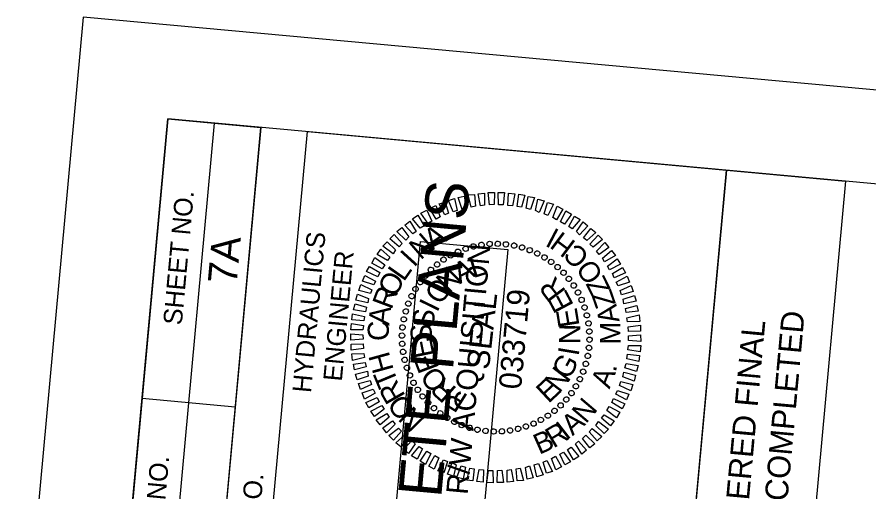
# Model space of a CAD drawing. Extents: x 2011671 to 2012922, y 444832 to 446720.
# Drawn here: x 2011808.5 to 2012036.3, y 446593.3 to 446720.2 of the extents above; entities that cross this region are included whole.
import ezdxf

# ---------------------------------------------------------------- set-up
doc = ezdxf.new("R2010")
doc.units = 0
for name, color, linetype in [('Sheet Data Field CELL', 7, 'Continuous'), ('Sheet Plan And Profile CELL', 7, 'Continuous'), ('Sheet Plot Border Outside CELL', 7, 'Continuous'), ('Sheet Professional Seal CELL', 7, 'Continuous'), ('Sheet Profile Grid Minor CELL', 7, 'Continuous'), ('Sheet Sticker Exception Certification CELL', 7, 'Continuous'), ('Sheet Sticker Incomplete CELL', 7, 'Continuous')]:
    doc.layers.add(name, color=color, linetype=linetype)

msp = doc.modelspace()

# ---------------------------------------------------------------- linework, layer by layer
at = {"layer": 'Sheet Plan And Profile CELL'}
for p, q in [((2011842.98, 446492.7), (2011861.29, 446691.91)), ((2011855.42, 446491.55), (2011873.74, 446690.76)), ((2011841.98, 446618.37), (2011866.87, 446616.08))]:
    msp.add_line(p, q, dxfattribs=at)
for points in [[(2011848.79, 446693.05), (2011711.46, 445199.36), (2012757.04, 445103.22), (2012894.38, 446596.92)], [(2011830.48, 446493.85), (2011848.79, 446693.05), (2011873.74, 446690.76), (2011855.42, 446491.55)], [(2011877.03, 446590.04), (2011886.19, 446689.62), (2011998.21, 446679.32), (2011989.06, 446579.74)]]:
    msp.add_lwpolyline(points, close=True, dxfattribs=at)
at = {"layer": 'Sheet Plot Border Outside CELL'}
msp.add_lwpolyline([(2012765.92, 444926.66), (2012921.57, 446619.52), (2011826.19, 446720.24), (2011670.54, 445027.38)], close=True, dxfattribs=at)
at = {"layer": 'Sheet Professional Seal CELL'}
for p, q in [((2011928.46, 446658.36), (2011928.46, 446658.36)), ((2011930.53, 446658.97), (2011930.53, 446658.97)), ((2011932.67, 446659.38), (2011932.67, 446659.38)), ((2011934.9, 446659.57), (2011934.9, 446659.57)), ((2011937.07, 446659.68), (2011937.07, 446659.68)), ((2011939.26, 446659.52), (2011939.26, 446659.52)), ((2011941.44, 446659.17), (2011941.44, 446659.17)), ((2011943.55, 446658.63), (2011943.55, 446658.63)), ((2011945.6, 446657.99), (2011945.6, 446657.99)), ((2011922.57, 446655.48), (2011922.57, 446655.48)), ((2011924.43, 446656.57), (2011924.43, 446656.57)), ((2011926.43, 446657.54), (2011926.43, 446657.54)), ((2011947.63, 446657.1), (2011947.63, 446657.1)), ((2011949.54, 446656.02), (2011949.54, 446656.02)), ((2011920.79, 446654.14), (2011920.79, 446654.14)), ((2011951.39, 446654.84), (2011951.39, 446654.84)), ((2011953.06, 446653.43), (2011953.06, 446653.43)), ((2011917.65, 446651.12), (2011917.65, 446651.12)), ((2011919.16, 446652.74), (2011919.16, 446652.74)), ((2011954.68, 446651.93), (2011954.68, 446651.93)), ((2011916.24, 446649.44), (2011916.24, 446649.44)), ((2011956.09, 446650.29), (2011956.09, 446650.29)), ((2011915.07, 446647.59), (2011915.07, 446647.59)), ((2011957.43, 446648.51), (2011957.43, 446648.51)), ((2011958.52, 446646.66), (2011958.52, 446646.66)), ((2011913.99, 446645.68), (2011913.99, 446645.68)), ((2011959.49, 446644.66), (2011959.49, 446644.66)), ((2011913.1, 446643.65), (2011913.1, 446643.65)), ((2011960.3, 446642.63), (2011960.3, 446642.63)), ((2011911.91, 446639.49), (2011911.91, 446639.49)), ((2011912.46, 446641.6), (2011912.46, 446641.6)), ((2011960.92, 446640.56), (2011960.92, 446640.56)), ((2011911.56, 446637.32), (2011911.56, 446637.32)), ((2011961.32, 446638.42), (2011961.32, 446638.42)), ((2011911.41, 446635.12), (2011911.41, 446635.12)), ((2011961.52, 446636.19), (2011961.52, 446636.19)), ((2011911.51, 446632.95), (2011911.51, 446632.95)), ((2011936.52, 446634.57), (2011936.52, 446634.57)), ((2011961.62, 446634.02), (2011961.62, 446634.02)), ((2011911.71, 446630.73), (2011911.71, 446630.73)), ((2011961.47, 446631.82), (2011961.47, 446631.82)), ((2011912.12, 446628.58), (2011912.12, 446628.58)), ((2011961.12, 446629.65), (2011961.12, 446629.65)), ((2011912.73, 446626.51), (2011912.73, 446626.51)), ((2011960.57, 446627.54), (2011960.57, 446627.54)), ((2011913.55, 446624.48), (2011913.55, 446624.48)), ((2011959.93, 446625.49), (2011959.93, 446625.49)), ((2011914.52, 446622.48), (2011914.52, 446622.48)), ((2011957.96, 446621.55), (2011957.96, 446621.55)), ((2011959.04, 446623.46), (2011959.04, 446623.46)), ((2011915.6, 446620.63), (2011915.6, 446620.63)), ((2011956.79, 446619.7), (2011956.79, 446619.7)), ((2011916.94, 446618.85), (2011916.94, 446618.85)), ((2011918.35, 446617.21), (2011918.35, 446617.21)), ((2011955.38, 446618.02), (2011955.38, 446618.02)), ((2011919.97, 446615.71), (2011919.97, 446615.71)), ((2011952.24, 446615), (2011952.24, 446615)), ((2011953.88, 446616.4), (2011953.88, 446616.4)), ((2011921.65, 446614.3), (2011921.65, 446614.3)), ((2011923.5, 446613.12), (2011923.5, 446613.12)), ((2011948.6, 446612.57), (2011948.6, 446612.57)), ((2011950.46, 446613.66), (2011950.46, 446613.66)), ((2011925.41, 446612.04), (2011925.41, 446612.04)), ((2011927.43, 446611.15), (2011927.43, 446611.15)), ((2011929.48, 446610.51), (2011929.48, 446610.51)), ((2011931.59, 446609.97), (2011931.59, 446609.97)), ((2011942.51, 446610.17), (2011942.51, 446610.17)), ((2011944.57, 446610.78), (2011944.57, 446610.78)), ((2011946.61, 446611.6), (2011946.61, 446611.6)), ((2011933.77, 446609.62), (2011933.77, 446609.62)), ((2011935.97, 446609.47), (2011935.97, 446609.47)), ((2011938.13, 446609.57), (2011938.13, 446609.57)), ((2011940.36, 446609.76), (2011940.36, 446609.76))]:
    msp.add_line(p, q, dxfattribs=at)
for points in [[(2011925.09, 446668.16), (2011923.87, 446671.23), (2011925.52, 446671.73), (2011926.23, 446668.55)], [(2011927.52, 446668.84), (2011926.5, 446671.99), (2011928.09, 446672.4), (2011928.61, 446669.24)], [(2011929.98, 446669.42), (2011929.13, 446672.71), (2011930.8, 446672.85), (2011931.06, 446669.67)], [(2011932.42, 446669.79), (2011931.77, 446673.02), (2011933.49, 446673.16), (2011933.5, 446670)], [(2011934.86, 446670.02), (2011934.46, 446673.32), (2011936.16, 446673.32), (2011936.07, 446670.11)], [(2011937.27, 446670.1), (2011937.17, 446673.37), (2011938.87, 446673.32), (2011938.48, 446670.09)], [(2011939.77, 446669.92), (2011939.92, 446673.17), (2011941.61, 446673.02), (2011940.96, 446669.81)], [(2011942.25, 446669.64), (2011942.65, 446672.87), (2011944.28, 446672.62), (2011943.44, 446669.43)], [(2011944.62, 446669.17), (2011945.21, 446672.33), (2011946.89, 446671.98), (2011945.79, 446668.81)], [(2011947.12, 446668.54), (2011947.8, 446671.59), (2011949.46, 446671.09), (2011948.13, 446668.05)], [(2011920.55, 446666.27), (2011918.9, 446669.08), (2011920.48, 446669.89), (2011921.61, 446666.87)], [(2011922.86, 446667.36), (2011921.37, 446670.31), (2011922.98, 446670.81), (2011923.86, 446667.87)], [(2011949.45, 446667.67), (2011950.38, 446670.7), (2011951.99, 446670.2), (2011950.46, 446667.18)], [(2011951.77, 446666.71), (2011952.95, 446669.71), (2011954.44, 446668.92), (2011952.77, 446666.06)], [(2011916.31, 446663.84), (2011914.28, 446666.34), (2011915.72, 446667.26), (2011917.37, 446664.45)], [(2011918.39, 446665.16), (2011916.52, 446667.79), (2011918.06, 446668.6), (2011919.39, 446665.67)], [(2011953.87, 446665.51), (2011955.3, 446668.49), (2011956.78, 446667.6), (2011954.92, 446664.91)], [(2011956.07, 446664.3), (2011957.58, 446667.03), (2011959.05, 446666.14), (2011956.96, 446663.62)], [(2011914.36, 446662.27), (2011912.22, 446664.62), (2011913.52, 446665.71), (2011915.22, 446662.94)], [(2011958.1, 446662.91), (2011959.85, 446665.56), (2011961.15, 446664.44), (2011958.93, 446662.03)], [(2011912.45, 446660.63), (2011910.05, 446662.91), (2011911.36, 446664), (2011913.29, 446661.51)], [(2011959.96, 446661.24), (2011961.9, 446663.77), (2011963.25, 446662.69), (2011960.84, 446660.5)], [(2011909.05, 446656.98), (2011906.33, 446658.99), (2011907.49, 446660.19), (2011909.75, 446658.02)], [(2011910.73, 446658.88), (2011908.17, 446660.98), (2011909.38, 446662.17), (2011911.52, 446659.76)], [(2011961.71, 446659.57), (2011963.89, 446661.98), (2011965.08, 446660.76), (2011962.54, 446658.79)], [(2011963.44, 446657.65), (2011965.72, 446660), (2011966.75, 446658.65), (2011964.17, 446656.78)], [(2011907.53, 446655.16), (2011904.82, 446656.77), (2011905.8, 446658.18), (2011908.21, 446656.05)], [(2011965.03, 446655.85), (2011967.43, 446657.84), (2011968.51, 446656.53), (2011965.64, 446654.84)], [(2011906.17, 446652.98), (2011903.35, 446654.49), (2011904.19, 446655.97), (2011906.82, 446654.02)], [(2011966.39, 446653.71), (2011968.98, 446655.64), (2011969.9, 446654.2), (2011966.96, 446652.71)], [(2011905.02, 446650.82), (2011901.99, 446652.26), (2011902.72, 446653.59), (2011905.48, 446651.94)], [(2011967.71, 446651.69), (2011970.42, 446653.29), (2011971.25, 446651.91), (2011968.21, 446650.54)], [(2011903.92, 446648.66), (2011900.9, 446649.69), (2011901.54, 446651.19), (2011904.36, 446649.68)], [(2011968.76, 446649.38), (2011971.62, 446650.98), (2011972.27, 446649.36), (2011969.27, 446648.38)], [(2011903.05, 446646.33), (2011899.86, 446647.13), (2011900.42, 446648.79), (2011903.4, 446647.36)], [(2011969.76, 446647.13), (2011972.69, 446648.47), (2011973.25, 446646.86), (2011970.1, 446645.99)], [(2011902.27, 446643.84), (2011899.13, 446644.59), (2011899.53, 446646.21), (2011902.53, 446645.03)], [(2011970.6, 446644.84), (2011973.61, 446645.87), (2011974.07, 446644.32), (2011970.78, 446643.57)], [(2011901.65, 446641.49), (2011898.44, 446641.99), (2011898.89, 446643.6), (2011901.96, 446642.67)], [(2011971.17, 446642.33), (2011974.27, 446643.2), (2011974.57, 446641.62), (2011971.42, 446641.25)], [(2011901.28, 446639.02), (2011898.04, 446639.31), (2011898.24, 446640.95), (2011901.44, 446640.21)], [(2011971.6, 446639.88), (2011974.83, 446640.64), (2011975.03, 446638.91), (2011971.75, 446638.81)], [(2011901.01, 446636.63), (2011897.75, 446636.68), (2011897.95, 446638.32), (2011901.17, 446637.82)], [(2011971.93, 446637.44), (2011975.19, 446637.94), (2011975.19, 446636.29), (2011971.97, 446636.23)], [(2011901.03, 446634.12), (2011897.79, 446633.86), (2011897.75, 446635.57), (2011900.99, 446635.33)], [(2011972.01, 446635.02), (2011975.24, 446635.28), (2011975.29, 446633.57), (2011972.05, 446633.81)], [(2011901.11, 446631.7), (2011897.85, 446631.2), (2011897.85, 446632.85), (2011901.07, 446632.91)], [(2011901.43, 446629.26), (2011898.2, 446628.5), (2011898.01, 446630.23), (2011901.28, 446630.33)], [(2011972.03, 446632.51), (2011975.29, 446632.46), (2011975.09, 446630.82), (2011971.87, 446631.32)], [(2011971.76, 446630.12), (2011974.99, 446629.83), (2011974.79, 446628.19), (2011971.6, 446628.93)], [(2011901.86, 446626.81), (2011898.77, 446625.94), (2011898.46, 446627.52), (2011901.61, 446627.89)], [(2011971.38, 446627.65), (2011974.6, 446627.15), (2011974.15, 446625.54), (2011971.07, 446626.47)], [(2011902.43, 446624.3), (2011899.43, 446623.27), (2011898.97, 446624.82), (2011902.25, 446625.57)], [(2011970.76, 446625.3), (2011973.91, 446624.55), (2011973.51, 446622.93), (2011970.5, 446624.11)], [(2011903.28, 446622.01), (2011900.34, 446620.67), (2011899.79, 446622.28), (2011902.93, 446623.15)], [(2011969.98, 446622.81), (2011973.17, 446622.01), (2011972.62, 446620.36), (2011969.63, 446621.78)], [(2011904.28, 446619.76), (2011901.42, 446618.17), (2011900.76, 446619.78), (2011903.76, 446620.76)], [(2011969.11, 446620.48), (2011972.13, 446619.45), (2011971.49, 446617.95), (2011968.67, 446619.46)], [(2011905.32, 446617.45), (2011902.61, 446615.85), (2011901.78, 446617.23), (2011904.82, 446618.61)], [(2011968.01, 446618.32), (2011971.04, 446616.88), (2011970.32, 446615.55), (2011967.56, 446617.21)], [(2011906.64, 446615.43), (2011904.05, 446613.5), (2011903.13, 446614.94), (2011906.08, 446616.43)], [(2011966.86, 446616.16), (2011969.68, 446614.65), (2011968.84, 446613.17), (2011966.21, 446615.12)], [(2011908, 446613.29), (2011905.61, 446611.3), (2011904.52, 446612.61), (2011907.39, 446614.3)], [(2011909.59, 446611.49), (2011907.32, 446609.14), (2011906.28, 446610.49), (2011908.87, 446612.36)], [(2011963.98, 446612.16), (2011966.71, 446610.15), (2011965.54, 446608.95), (2011963.28, 446611.12)], [(2011965.5, 446613.98), (2011968.22, 446612.37), (2011967.23, 446610.96), (2011964.82, 446613.09)], [(2011911.32, 446609.57), (2011909.14, 446607.16), (2011907.95, 446608.38), (2011910.49, 446610.35)], [(2011962.3, 446610.26), (2011964.87, 446608.16), (2011963.65, 446606.97), (2011961.51, 446609.38)], [(2011913.08, 446607.9), (2011911.14, 446605.37), (2011909.78, 446606.45), (2011912.19, 446608.64)], [(2011960.58, 446608.51), (2011962.98, 446606.23), (2011961.68, 446605.14), (2011959.75, 446607.63)], [(2011914.93, 446606.23), (2011913.18, 446603.58), (2011911.88, 446604.7), (2011914.11, 446607.11)], [(2011916.96, 446604.84), (2011915.46, 446602.11), (2011913.98, 446603), (2011916.07, 446605.52)], [(2011956.72, 446605.3), (2011958.75, 446602.8), (2011957.31, 446601.88), (2011955.66, 446604.69)], [(2011958.67, 446606.88), (2011960.82, 446604.52), (2011959.51, 446603.43), (2011957.81, 446606.2)], [(2011919.16, 446603.63), (2011917.73, 446600.65), (2011916.26, 446601.54), (2011918.11, 446604.23)], [(2011921.26, 446602.43), (2011920.08, 446599.43), (2011918.6, 446600.22), (2011920.26, 446603.08)], [(2011954.64, 446603.98), (2011956.51, 446601.35), (2011954.98, 446600.54), (2011953.64, 446603.47)], [(2011923.58, 446601.47), (2011922.65, 446598.44), (2011921.04, 446598.94), (2011922.57, 446601.96)], [(2011925.91, 446600.6), (2011925.23, 446597.55), (2011923.57, 446598.05), (2011924.9, 446601.09)], [(2011947.94, 446600.98), (2011949.16, 446597.91), (2011947.51, 446597.41), (2011946.8, 446600.59)], [(2011950.17, 446601.78), (2011951.66, 446598.83), (2011950.06, 446598.33), (2011949.17, 446601.27)], [(2011952.48, 446602.88), (2011954.13, 446600.06), (2011952.55, 446599.25), (2011951.42, 446602.27)], [(2011928.41, 446599.97), (2011927.82, 446596.81), (2011926.15, 446597.16), (2011927.24, 446600.33)], [(2011930.78, 446599.5), (2011930.38, 446596.27), (2011928.75, 446596.52), (2011929.6, 446599.71)], [(2011933.27, 446599.22), (2011933.12, 446595.97), (2011931.43, 446596.12), (2011932.07, 446599.33)], [(2011935.76, 446599.04), (2011935.86, 446595.77), (2011934.16, 446595.82), (2011934.56, 446599.05)], [(2011938.18, 446599.12), (2011938.58, 446595.82), (2011936.87, 446595.83), (2011936.96, 446599.03)], [(2011940.61, 446599.35), (2011941.27, 446596.12), (2011939.55, 446595.98), (2011939.54, 446599.14)], [(2011943.05, 446599.73), (2011943.91, 446596.43), (2011942.24, 446596.29), (2011941.98, 446599.47)], [(2011945.52, 446600.3), (2011946.53, 446597.15), (2011944.94, 446596.74), (2011944.43, 446599.9)]]:
    msp.add_lwpolyline(points, close=True, dxfattribs=at)
for centre, major_axis in [((2011932.7, 446659.36), (-0.109, 0.712)), ((2011934.88, 446659.6), (-0.047, 0.718)), ((2011937.07, 446659.64), (0.016, 0.72)), ((2011939.25, 446659.5), (0.078, 0.716)), ((2011941.41, 446659.17), (0.141, 0.706)), ((2011926.42, 446657.53), (-0.29, 0.659)), ((2011928.46, 446658.32), (-0.231, 0.682)), ((2011930.56, 446658.93), (-0.171, 0.699)), ((2011943.54, 446658.65), (0.202, 0.691)), ((2011945.61, 446657.94), (0.261, 0.671)), ((2011947.61, 446657.06), (0.318, 0.646)), ((2011922.58, 446655.42), (-0.4, 0.599)), ((2011924.45, 446656.56), (-0.346, 0.631)), ((2011949.53, 446656.01), (0.374, 0.616)), ((2011951.35, 446654.79), (0.426, 0.581)), ((2011919.17, 446652.69), (-0.498, 0.52)), ((2011920.82, 446654.13), (-0.451, 0.562)), ((2011953.05, 446653.43), (0.475, 0.541)), ((2011917.66, 446651.11), (-0.541, 0.475)), ((2011954.63, 446651.91), (0.52, 0.498)), ((2011956.08, 446650.27), (0.562, 0.451)), ((2011916.29, 446649.4), (-0.581, 0.426)), ((2011957.37, 446648.5), (0.599, 0.4)), ((2011914.02, 446645.66), (-0.646, 0.318)), ((2011915.08, 446647.58), (-0.616, 0.374)), ((2011958.51, 446646.63), (0.631, 0.346)), ((2011913.14, 446643.66), (-0.671, 0.261)), ((2011959.47, 446644.67), (0.659, 0.29)), ((2011912.44, 446641.59), (-0.691, 0.202)), ((2011960.27, 446642.63), (0.682, 0.231)), ((2011911.92, 446639.46), (-0.706, 0.141)), ((2011960.88, 446640.53), (0.699, 0.171)), ((2011911.59, 446637.3), (-0.716, 0.078)), ((2011961.3, 446638.38), (0.712, 0.109)), ((2011911.44, 446635.12), (-0.72, 0.016)), ((2011961.54, 446636.21), (0.718, 0.047)), ((2011911.49, 446632.93), (-0.718, -0.047)), ((2011961.59, 446634.02), (0.72, -0.016)), ((2011911.73, 446630.76), (-0.712, -0.109)), ((2011961.11, 446629.68), (0.706, -0.141)), ((2011961.45, 446631.84), (0.716, -0.078)), ((2011912.15, 446628.61), (-0.699, -0.171)), ((2011960.59, 446627.55), (0.691, -0.202)), ((2011912.77, 446626.51), (-0.682, -0.231)), ((2011959.89, 446625.48), (0.671, -0.261)), ((2011913.56, 446624.47), (-0.659, -0.29)), ((2011959.01, 446623.48), (0.646, -0.318)), ((2011914.53, 446622.51), (-0.631, -0.346)), ((2011915.66, 446620.64), (-0.599, -0.4)), ((2011957.96, 446621.56), (0.616, -0.374)), ((2011916.96, 446618.87), (-0.562, -0.451)), ((2011956.74, 446619.74), (0.581, -0.426)), ((2011918.4, 446617.23), (-0.52, -0.498)), ((2011953.86, 446616.45), (0.498, -0.52)), ((2011955.37, 446618.03), (0.541, -0.475)), ((2011919.98, 446615.72), (-0.475, -0.541)), ((2011921.69, 446614.35), (-0.426, -0.581)), ((2011950.45, 446613.72), (0.4, -0.599)), ((2011952.21, 446615.01), (0.451, -0.562)), ((2011923.5, 446613.13), (-0.374, -0.616)), ((2011925.42, 446612.08), (-0.318, -0.646)), ((2011946.62, 446611.61), (0.29, -0.659)), ((2011948.58, 446612.58), (0.346, -0.631)), ((2011927.43, 446611.2), (-0.261, -0.671)), ((2011929.5, 446610.49), (-0.202, -0.691)), ((2011931.62, 446609.97), (-0.141, -0.706)), ((2011933.78, 446609.64), (-0.078, -0.716)), ((2011935.97, 446609.5), (-0.016, -0.72)), ((2011938.16, 446609.54), (0.047, -0.718)), ((2011940.33, 446609.78), (0.109, -0.712)), ((2011942.48, 446610.21), (0.171, -0.699)), ((2011944.58, 446610.82), (0.231, -0.682))]:
    msp.add_ellipse(centre, major_axis=major_axis, ratio=0.999708, dxfattribs=at)
at = {"layer": 'Sheet Sticker Exception Certification CELL'}
for p, q in [((2011979.88, 446480.11), (2011998.2, 446679.32)), ((2011998.21, 446679.32), (2012030.06, 446676.39)), ((2012030.04, 446676.39), (2012011.73, 446477.18))]:
    msp.add_line(p, q, dxfattribs=at)
at = {"layer": 'Sheet Sticker Incomplete CELL'}
msp.add_lwpolyline([(2011926.32, 446511.7), (2011902.91, 446513.85), (2011916.37, 446660.23), (2011939.77, 446658.08)], close=True, dxfattribs=at)

# ---------------------------------------------------------------- texts
at = {"layer": 'Sheet Data Field CELL'}
msp.add_text('7A', height=7.75, rotation=84.7467, dxfattribs=at).set_placement((2011867.21, 446648.68))
at = {"layer": 'Sheet Plan And Profile CELL'}
for s, height, p in [('SHEET NO.', 5, (2011852.55, 446637.78)), ('HYDRAULICS', 5, (2011887.09, 446619.69)), ('ENGINEER', 5, (2011895.35, 446622.75)), ('PROJECT REFERENCE NO.', 5.0001, (2011841.17, 446515.16)), ('R/W SHEET NO.', 5.0001, (2011869.8, 446547.47))]:
    msp.add_text(s, height=height, rotation=84.7467, dxfattribs=at).set_placement(p)
at = {"layer": 'Sheet Professional Seal CELL'}
for s, height, rotation, p in [('N', 5.64, 40.5656, (2011916.42, 446655.15)), ('A', 5.64, 33.3638, (2011919.62, 446657.81)), ('I', 5.64, 47.7668, (2011914.68, 446653.15)), ('L', 5.64, 17.1475, (2011930.49, 446650.44)), ('L', 5.64, 54.9675, (2011911.92, 446649.33)), ('N', 5.64, 45.2233, (2011924.03, 446646.21)), ('A', 5.64, 26.5069, (2011926.88, 446648.81)), ('O', 5.64, 62.1678, (2011909.67, 446645.12)), ('R', 5.64, 127.2281, (2011955.48, 446646.99)), ('O', 5.64, 54.5801, (2011921.73, 446643.06)), ('R', 5.64, 69.3678, (2011908.62, 446641.86)), ('E', 5.64, 117.8707, (2011957.5, 446643.24)), ('I', 5.64, 63.9363, (2011920.85, 446641.13)), ('SEAL', 5.998, 83.7467, (2011934.71, 446625.85)), ('A', 5.64, 83.767, (2011908.03, 446637.69)), ('S', 5.64, 82.6471, (2011919.76, 446636.91)), ('E', 5.64, 99.1584, (2011958.95, 446637.78)), ('C', 5.64, 90.9665, (2011907.97, 446633.73)), ('S', 5.64, 92.0023, (2011919.48, 446633.32)), ('N', 5.64, 89.803, (2011959.1, 446632.8)), ('E', 5.64, 101.3577, (2011920.21, 446629.79)), ('H', 5.64, 105.3661, (2011909.27, 446625.98)), ('I', 5.64, 80.4479, (2011958.64, 446629.47)), ('F', 5.64, 110.7137, (2011921.41, 446626.47)), ('G', 5.64, 61.7369, (2011956.15, 446623.12)), ('O', 5.64, 129.4279, (2011924.05, 446622.91)), ('N', 5.64, 52.3806, (2011953.56, 446619.55)), ('T', 5.64, 112.5664, (2011910.61, 446622.59)), ('R', 5.64, 138.7863, (2011926.33, 446620.95)), ('E', 5.64, 43.0235, (2011950.6, 446616.81)), ('R', 5.64, 119.7672, (2011912.49, 446619)), ('P', 5.64, 148.1455, (2011929.37, 446619.06)), ('O', 5.64, 126.9684, (2011915.26, 446615.29)), ('N', 5.64, 134.1702, (2011917.94, 446612.73))]:
    msp.add_text(s, height=height, rotation=rotation, dxfattribs=at).set_placement(p)
at = {"layer": 'Sheet Profile Grid Minor CELL'}
for s, height, rotation, p in [('I', 5.5, 152.3393, (2011953.84, 446663.16)), ('H', 5.5, 143.0945, (2011958.21, 446660)), ('C', 5.5, 134.2218, (2011961.87, 446656.35)), ('O', 5.5, 123.5173, (2011965.48, 446651.26)), ('Z', 5.5, 116.3905, (2011967.33, 446647.54)), ('033719', 5.998, 84.7467, (2011943.27, 446620.58)), ('Z', 5.5, 109.2637, (2011968.7, 446643.62)), ('A', 5.5, 101.0779, (2011969.66, 446638.94)), ('M', 5.5, 90.402, (2011969.89, 446632.73)), ('.', 5.5, 77.2217, (2011968.6, 446625.17)), ('A', 5.5, 69.0359, (2011966.93, 446620.7)), ('N', 5.5, 49.6591, (2011960.6, 446611.39)), ('I', 5.5, 37.9528, (2011955.4, 446606.99)), ('A', 5.5, 41.4733, (2011957.06, 446608.2)), ('B', 5.5, 23.8996, (2011948.14, 446603.23)), ('R', 5.5, 31.0264, (2011951.94, 446604.91))]:
    msp.add_text(s, height=height, rotation=rotation, dxfattribs=at).set_placement(p)
at = {"layer": 'Sheet Sticker Exception Certification CELL'}
for s, p in [('UNLESS ALL SIGNATURES COMPLETED', (2012004.66, 446483.75)), ('DOCUMENT NOT CONSIDERED FINAL', (2011994.97, 446490.4))]:
    msp.add_text(s, height=6.124, rotation=84.7467, dxfattribs=at).set_placement(p)
at = {"layer": 'Sheet Sticker Incomplete CELL'}
for s, height, p in [('INCOMPLETE PLANS', 11.52, (2011915.48, 446521.68)), ('DO NOT USE FOR R/W ACQUISITION', 5.76, (2011922.7, 446524.28))]:
    msp.add_text(s, height=height, rotation=84.7467, dxfattribs=at).set_placement(p)

doc.saveas('drawing.dxf')
